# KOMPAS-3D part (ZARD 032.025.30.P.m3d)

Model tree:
1. Плоскость XY
2. Плоскость ZX
3. Плоскость ZY
4. Ось X
5. Ось Y
6. Ось Z
7. Начало координат
8. Булева операция:1
9. Булева операция:2
10. Булева операция:3
11. Булева операция:4
12. Булева операция:5
13. Булева операция:6
